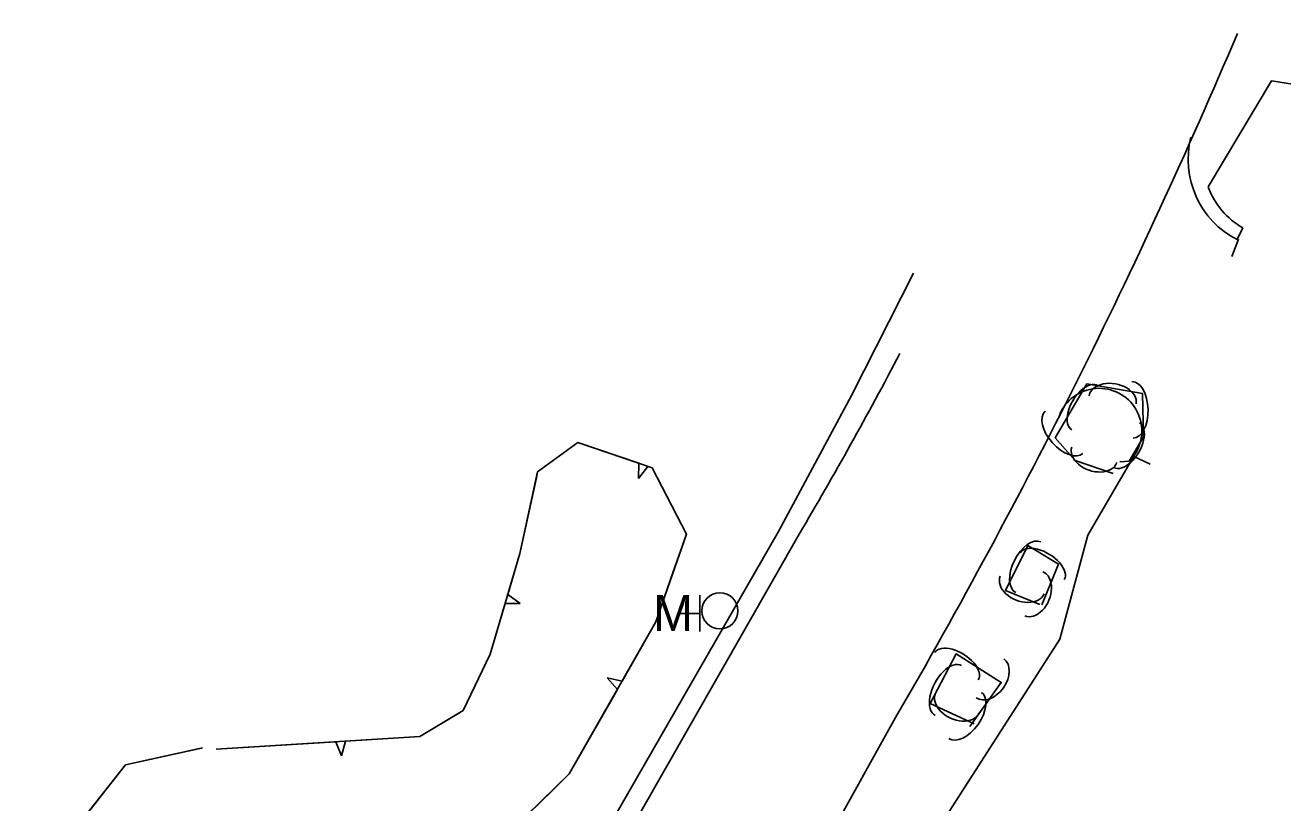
# Model space of a CAD drawing. Extents: x 978516 to 993312, y 1836504 to 1846212.
# Drawn here: x 980949.8 to 981210.9, y 1842711.2 to 1842872.7 of the extents above; entities that cross this region are included whole.
import ezdxf

# ---------------------------------------------------------------- set-up
doc = ezdxf.new("R2010")
doc.units = 0
for name, color, linetype in [('S_CURB', 7, 'Continuous'), ('S_EDGE_PAVEMENT', 7, 'Continuous'), ('S_MANHOLE', 7, 'Continuous'), ('S_PARKING', 7, 'Continuous'), ('S_SIDEWALK', 7, 'Continuous'), ('S_TREE', 7, 'Continuous')]:
    doc.layers.add(name, color=color, linetype=linetype)

msp = doc.modelspace()

# ---------------------------------------------------------------- linework, layer by layer
at = {"layer": 'S_CURB'}
for points in [[(981201.69, 1842828.27), (981200.26, 1842824.66)], [(981179.68, 1842783.27), (981183.37, 1842781.5)]]:
    msp.add_lwpolyline(points, dxfattribs=at)
at = {"layer": 'S_EDGE_PAVEMENT'}
for points in [[(981031.55, 1842627.34), (981039.23, 1842641.83), (981060.58, 1842679.47), (981110.46, 1842767)], [(981130.49, 1842728.89), (981102.61, 1842678.82), (981075.29, 1842623.01)]]:
    msp.add_lwpolyline(points, dxfattribs=at)
for centre, major_axis, ratio, start_param, end_param in [((980053.97, 1843348.73), (739.68, 1020.52), 0.985417, 4.815631, 4.941758), ((980850.04, 1842970.44), (221.22, 462.05), 0.636152, 4.573275, 4.6574)]:
    msp.add_ellipse(centre, major_axis=major_axis, ratio=ratio, start_param=start_param, end_param=end_param, dxfattribs=at)
at = {"layer": 'S_MANHOLE'}
for p, q in [((981089.81, 1842746.8), (981089.81, 1842754.3)), ((981085.63, 1842750.51), (981089.81, 1842750.51))]:
    msp.add_line(p, q, dxfattribs=at)
msp.add_circle((981094.01, 1842751.07), 3.75, dxfattribs=at)
at = {"layer": 'S_PARKING'}
for points in [[(981225.09, 1842872.7), (981228.04, 1842860.91), (981226.77, 1842858.26), (981208.5, 1842861.11), (981195.4, 1842839.09)], [(981202.59, 1842830.63), (981201.41, 1842828.17)], [(981180.17, 1842783.55), (981170.38, 1842766.78), (981164.56, 1842745.16), (981113.29, 1842665.27)]]:
    msp.add_lwpolyline(points, dxfattribs=at)
for centre, major_axis, ratio, start_param, end_param in [((981208.3, 1842844.26), (5.77, -17.02), 0.944417, 4.107327, 5.523511), ((981210.13, 1842844.35), (8.81, -13.08), 0.991251, 4.464952, 5.184372), ((981172.74, 1842788.41), (-6.51, 6.03), 0.999094, 3.308788, 6.656561)]:
    msp.add_ellipse(centre, major_axis=major_axis, ratio=ratio, start_param=start_param, end_param=end_param, dxfattribs=at)
at = {"layer": 'S_SIDEWALK'}
msp.add_lwpolyline([(981027.52, 1842629.11), (981047.19, 1842664.94), (981106.16, 1842767.52), (981121.33, 1842795.8), (981134.18, 1842821.16)], dxfattribs=at)
at = {"layer": 'S_TREE'}
for p, q in [((981077.18, 1842781.7), (981077.1, 1842778.56)), ((981077.1, 1842778.56), (981079.04, 1842781.06)), ((981052.54, 1842752.61), (981049.95, 1842754.44)), ((981049.4, 1842752.56), (981052.54, 1842752.61)), ((981073.7, 1842736.45), (981070.63, 1842737.12)), ((981070.63, 1842737.12), (981072.73, 1842734.75)), ((981014.29, 1842723.87), (981015.42, 1842720.93)), ((981015.42, 1842720.93), (981016.25, 1842723.99))]:
    msp.add_line(p, q, dxfattribs=at)
for points in [[(981175.65, 1842779.62), (981167.8, 1842782.31), (981163.64, 1842786.97), (981170.21, 1842798.2), (981181.73, 1842796.23), (981181.93, 1842787.21), (981179.01, 1842782.16), (981177.02, 1842782)], [(980989.44, 1842722.32), (981031.7, 1842724.95), (981040.68, 1842730.39), (981046.28, 1842742.05), (981052.48, 1842762.95), (981056.17, 1842779.93), (981064.5, 1842786.04), (981079.94, 1842780.75), (981087.04, 1842766.99), (981080.73, 1842748.79), (981062.74, 1842717.21), (981039.04, 1842694.09), (981018.5, 1842685.87), (980988.93, 1842684.75), (980978.38, 1842685.22), (980964.65, 1842677.82), (980955.47, 1842677.72), (980949.76, 1842687.92), (980955.46, 1842699.77), (980970.57, 1842719.07), (980986.58, 1842722.58)], [(981055.9, 1842778.71), (981056.17, 1842779.93), (981064.5, 1842786.04), (981077.18, 1842781.7)], [(981079.04, 1842781.06), (981079.94, 1842780.75), (981087.04, 1842766.99), (981084.26, 1842758.98)], [(981049.95, 1842754.44), (981052.48, 1842762.95), (981055.9, 1842778.71)], [(981160.44, 1842752.4), (981153.28, 1842755.26), (981157.92, 1842764.66), (981164.3, 1842760.76), (981160.85, 1842752.33)], [(981084.26, 1842758.98), (981080.73, 1842748.79), (981073.7, 1842736.45)], [(981039.77, 1842729.84), (981040.68, 1842730.39), (981046.28, 1842742.05), (981049.4, 1842752.56)], [(981146.79, 1842727.63), (981137.65, 1842731.85), (981143.07, 1842742.1), (981152.42, 1842736.2), (981145.92, 1842727.04)], [(981072.73, 1842734.75), (981062.74, 1842717.21), (981059.3, 1842713.85)], [(981016.25, 1842723.99), (981031.7, 1842724.95), (981039.77, 1842729.84)], [(980989.44, 1842722.32), (981014.29, 1842723.87)], [(980965.14, 1842712.14), (980970.57, 1842719.07), (980986.38, 1842722.53)], [(981059.3, 1842713.85), (981041.41, 1842696.39)], [(980951.44, 1842691.4), (980955.46, 1842699.77), (980965.14, 1842712.14)]]:
    msp.add_lwpolyline(points, dxfattribs=at)
for centre, major_axis, ratio, start_param, end_param in [((981169.77, 1842793.25), (-2.7, -4.61), 0.540651, 3.141568, 6.283161), ((981175.54, 1842794.87), (-4.89, 0.83), 0.685061, 3.141446, 6.283039), ((981179.68, 1842792.8), (-0.13, 5.87), 0.550079, 3.141593, 6.283185), ((981165.45, 1842788.12), (3.91, -4.38), 0.549983, 3.141593, 6.283185), ((981178.48, 1842785.47), (2.67, 4.63), 0.540835, 3.141859, 6.283452), ((981171.75, 1842783.48), (4.68, -1.6), 0.686525, 3.139368, 6.280961), ((981158.04, 1842760.11), (-2.6, -5.26), 0.550164, 3.141314, 6.282906), ((981160.94, 1842760.33), (-4.56, 2.79), 0.54054, 3.141532, 6.283125), ((981156.76, 1842756.44), (4.57, -1.81), 0.690247, 3.138047, 6.27964), ((981159.19, 1842754.58), (1.88, 4.58), 0.68524, 3.141404, 6.282997), ((981143.13, 1842739.55), (-4.52, 2.85), 0.540685, 3.141621, 6.283214), ((981141.46, 1842734.52), (-2.74, -5.19), 0.550206, 3.141505, 6.283098), ((981150.1, 1842737.04), (2.87, 4.04), 0.685331, 3.141549, 6.283141), ((981143.29, 1842731.87), (4.5, -2.08), 0.685298, 3.141544, 6.283137), ((981144.96, 1842729.34), (3.39, 4.79), 0.550096, 3.141566, 6.283158)]:
    msp.add_ellipse(centre, major_axis=major_axis, ratio=ratio, start_param=start_param, end_param=end_param, dxfattribs=at)

# ---------------------------------------------------------------- texts
at = {"layer": 'S_MANHOLE'}
msp.add_text('M', height=7.46, dxfattribs=at).set_placement((981080.12, 1842746.89))

doc.saveas('drawing.dxf')
